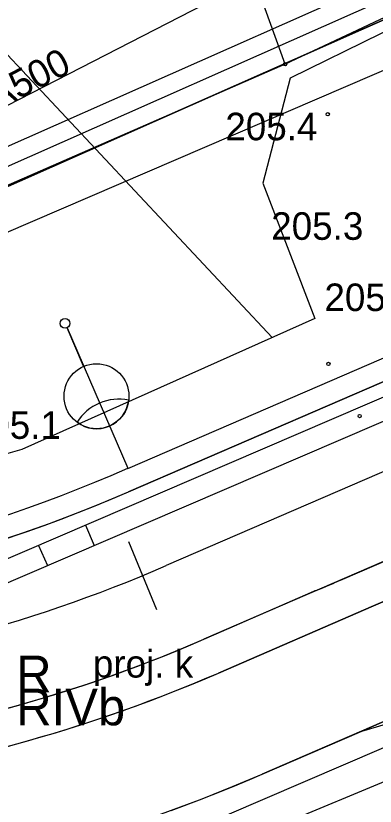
# Model space of a CAD drawing. Extents: x 6512606 to 6513006, y 6022524 to 6022728.
# Drawn here: x 6512832.56 to 6512842.35, y 6022578.56 to 6022600.08 of the extents above; entities that cross this region are included whole.
import ezdxf

# ---------------------------------------------------------------- set-up
doc = ezdxf.new("R2010")
doc.units = 0
for name, color, linetype in [('209-oznaczenie konturu klasyfikacyjnego', 7, 'Continuous'), ('210-oznaczenie konturu użytku gruntowego', 7, 'Continuous'), ('217-kontur klasyfikacyjny', 7, 'Continuous'), ('218-kontur użytku gruntowego', 7, 'Continuous'), ('219-działka ewidencyjna', 7, 'Continuous'), ('4', 7, 'Continuous'), ('Default', 7, 'Continuous'), ('E_OSW_KABLE', 7, 'Continuous'), ('E_OSW_LAMPA', 7, 'Continuous'), ('kolor_kostka_bet', 7, 'Continuous'), ('kolor_sc_rowerowa', 7, 'Continuous'), ('Level 60', 7, 'Continuous'), ('maxp_inst_energ', 7, 'Continuous'), ('maxp_kan_deszczowa', 7, 'Continuous'), ('maxp_krawężnik', 7, 'Continuous'), ('maxp_obrzeże', 7, 'Continuous'), ('maxp_opisy', 7, 'Continuous'), ('maxp_os', 7, 'Continuous'), ('maxp_ramka_2', 7, 'Continuous'), ('ogrodzenie trwałe', 7, 'Continuous'), ('pikieta naturalna', 7, 'Continuous'), ('pikieta naturalna-Atr2', 7, 'Continuous'), ('przewód kanalizacyjny', 7, 'Continuous'), ('przewód kanalizacyjny-Atr1', 7, 'Continuous'), ('punkt wysokościowy naturalny', 7, 'Continuous'), ('punkt wysokościowy naturalny-Atr2', 7, 'Continuous'), ('urządzenie techniczne projektowane lub w budowie (sieć kanalizacyjna) - powierzchnia - ob. projektowany', 7, 'Continuous'), ('urządzenie techniczne projektowane lub w budowie (sieć kanalizacyjna) - powierzchnia - ob. projektowany-Atr17', 7, 'Continuous')]:
    doc.layers.add(name, color=color, linetype=linetype)

# ---------------------------------------------------------------- blocks, each defined once
blk = doc.blocks.new('PW01')
at = {"layer": 'Default'}
blk.add_circle((0, 0), 0.45, dxfattribs=at)

msp = doc.modelspace()

# ---------------------------------------------------------------- linework, layer by layer
at = {"layer": '217-kontur klasyfikacyjny'}
for points in [[(6512811.09, 6022586.02), (6512848.55, 6022602.62)], [(6512848.55, 6022602.62), (6512811.09, 6022586.02)]]:
    msp.add_lwpolyline(points, dxfattribs=at)
at = {"layer": '218-kontur użytku gruntowego'}
for points in [[(6512811.09, 6022586.02), (6512848.55, 6022602.62)], [(6512848.55, 6022602.62), (6512811.09, 6022586.02)]]:
    msp.add_lwpolyline(points, dxfattribs=at)
at = {"layer": '219-działka ewidencyjna'}
msp.add_lwpolyline([(6512811.09, 6022586.02), (6512848.55, 6022602.62)], dxfattribs=at)
at = {"layer": '4'}
msp.add_lwpolyline([(6512811.09, 6022586.02), (6512848.55, 6022602.62)], dxfattribs=at)
at = {"layer": 'E_OSW_KABLE'}
for p, q in [((6512835.613, 6022587.752), (6512849.902, 6022593.935)), ((6512833.956, 6022591.584), (6512835.61, 6022587.761))]:
    msp.add_line(p, q, dxfattribs=at)
msp.add_arc((6512819.75, 6022623.828), 39.4, 271.0457, 293.7363, dxfattribs=at)
at = {"layer": 'E_OSW_LAMPA'}
msp.add_line((6512834.406, 6022590.54), (6512833.956, 6022591.584), dxfattribs=at)
for centre, radius in [((6512833.903, 6022591.705), 0.132), ((6512834.759, 6022589.721), 0.885)]:
    msp.add_circle(centre, radius, dxfattribs=at)
for centre, radius, start, end in [((6512835.378, 6022588.28), 1.362, 79.0115, 147.4701), ((6512834.759, 6022589.721), 0.885, 233.2408, 353.2408)]:
    msp.add_arc(centre, radius, start, end, dxfattribs=at)
at = {"layer": 'kolor_kostka_bet'}
for p, q in [((6512820.033, 6022589.983), (6512848.55, 6022602.62)), ((6512846.547, 6022591.839), (6512835.634, 6022587.117)), ((6512835.634, 6022587.117), (6512845.097, 6022591.211)), ((6512841.472, 6022584.74), (6512843.862, 6022585.774)), ((6512842.307, 6022584.011), (6512846.363, 6022585.766)), ((6512838.022, 6022583.247), (6512840.598, 6022584.378)), ((6512840.926, 6022584.517), (6512840.935, 6022584.514)), ((6512837.685, 6022583.102), (6512838.022, 6022583.247)), ((6512843.498, 6022581.258), (6512839.274, 6022579.431))]:
    msp.add_line(p, q, dxfattribs=at)
for points in [[(6512848.55, 6022602.62), (6512826.343, 6022592.779), (6512820.033, 6022589.983)], [(6512843.862, 6022585.774), (6512841.909, 6022584.929), (6512841.472, 6022584.74)], [(6512841.472, 6022584.74), (6512840.937, 6022584.508), (6512840.931, 6022584.506), (6512840.931, 6022584.506), (6512840.604, 6022584.364), (6512838.022, 6022583.247), (6512837.686, 6022583.102)], [(6512840.928, 6022584.511), (6512840.926, 6022584.517)], [(6512838.083, 6022582.184), (6512838.083, 6022582.184), (6512838.083, 6022582.184), (6512842.307, 6022584.011)], [(6512837.686, 6022583.102), (6512837.685, 6022583.102)]]:
    msp.add_lwpolyline(points, dxfattribs=at)
for centre, radius, start, end in [((6512819.75, 6022623.828), 40, 270.7527, 293.397), ((6512819.75, 6022623.828), 40, 270.7527, 293.397), ((6512829.559, 6022612.273), 30, 292.2834, 293.397), ((6512829.559, 6022612.273), 30, 293.3968, 293.397), ((6512829.559, 6022612.273), 30, 291.5902, 292.2701), ((6512821.802, 6022619.813), 40, 257.9783, 293.3967), ((6512821.802, 6022619.813), 40, 257.9783, 293.3967), ((6512821.802, 6022619.813), 41, 257.9783, 293.3967), ((6512821.802, 6022619.813), 44, 262.7977, 293.3967), ((6512821.802, 6022619.813), 44, 293.3967, 293.397)]:
    msp.add_arc(centre, radius, start, end, dxfattribs=at)
at = {"layer": 'kolor_sc_rowerowa'}
for p, q in [((6512846.363, 6022585.766), (6512842.307, 6022584.011)), ((6512842.307, 6022584.011), (6512838.083, 6022582.184)), ((6512839.274, 6022579.431), (6512843.498, 6022581.258))]:
    msp.add_line(p, q, dxfattribs=at)
msp.add_lwpolyline([(6512839.274, 6022579.431), (6512839.274, 6022579.43), (6512839.274, 6022579.43)], dxfattribs=at)
for radius, start, end in [(41, 257.9783, 293.397), (44, 262.7977, 293.3967), (44, 293.3967, 293.397), (44, 293.3967, 293.397)]:
    msp.add_arc((6512821.802, 6022619.813), radius, start, end, dxfattribs=at)
at = {"layer": 'Level 60'}
msp.add_lwpolyline([(6512835.635, 6022585.762), (6512836.397, 6022583.913)], dxfattribs=at)
at = {"layer": 'maxp_inst_energ'}
msp.add_line((6512828.214, 6022573.256), (6512855.354, 6022584.531), dxfattribs=at)
at = {"layer": 'maxp_kan_deszczowa'}
for points in [[(6512844.992, 6022600.824), (6512840.035, 6022598.38), (6512839.288, 6022595.519), (6512840.706, 6022591.84), (6512832.721, 6022588.268), (6512829.602, 6022587.385)], [(6512836.79, 6022578.444), (6512837.639, 6022578.762), (6512838.466, 6022579.091), (6512839.274, 6022579.43), (6512840.134, 6022579.803), (6512841.985, 6022580.604), (6512845.089, 6022581.521)]]:
    msp.add_lwpolyline(points, dxfattribs=at)
at = {"layer": 'maxp_krawężnik'}
for p, q in [((6512845.097, 6022591.211), (6512835.634, 6022587.117)), ((6512846.884, 6022587.081), (6512841.909, 6022584.929)), ((6512841.909, 6022584.929), (6512837.685, 6022583.102))]:
    msp.add_line(p, q, dxfattribs=at)
for centre, start in [((6512819.75, 6022623.828), 266.9005), ((6512821.802, 6022619.813), 262.7977)]:
    msp.add_arc(centre, 40, start, 293.397, dxfattribs=at)
at = {"layer": 'maxp_obrzeże'}
for p, q in [((6512846.363, 6022585.766), (6512842.307, 6022584.011)), ((6512842.307, 6022584.011), (6512838.083, 6022582.184)), ((6512843.498, 6022581.258), (6512839.274, 6022579.43))]:
    msp.add_line(p, q, dxfattribs=at)
for radius in [41, 44]:
    msp.add_arc((6512821.802, 6022619.813), radius, 262.7977, 293.397, dxfattribs=at)
at = {"layer": 'maxp_opisy'}
msp.add_line((6512839.545, 6022591.321), (6512830.726, 6022600.726), dxfattribs=at)
at = {"layer": 'maxp_os'}
msp.add_line((6512859.416, 6022594.955), (6512836.66, 6022585.109), dxfattribs=at)
msp.add_arc((6512820.776, 6022621.82), 40, 257.9783, 293.397, dxfattribs=at)
at = {"layer": 'maxp_ramka_2'}
for p, q in [((6512819.784, 6022590.966), (6512849.104, 6022603.959)), ((6512819.908, 6022590.475), (6512848.827, 6022603.29))]:
    msp.add_line(p, q, dxfattribs=at)
at = {"layer": 'ogrodzenie trwałe'}
for points in [[(6512847.46, 6022602.32), (6512839.9, 6022598.76), (6512838.38, 6022602.97)], [(6512839.9, 6022598.76), (6512827.97, 6022593.56), (6512815.03, 6022587.35), (6512805.68, 6022582.71), (6512799.86, 6022579.98), (6512797.99, 6022580.48)]]:
    msp.add_lwpolyline(points, dxfattribs=at)
at = {"layer": 'przewód kanalizacyjny'}
msp.add_lwpolyline([(6512821.92, 6022592.3), (6512839.38, 6022601.27), (6512844.43, 6022605.49), (6512845.59, 6022604.41), (6512846.7, 6022605.53), (6512847.74, 6022606.78)], dxfattribs=at)
at = {"layer": 'urządzenie techniczne projektowane lub w budowie (sieć kanalizacyjna) - powierzchnia - ob. projektowany'}
for points in [[(6512813.61, 6022586.15), (6512845.46, 6022599.83)], [(6512848.68, 6022592.32), (6512816.84, 6022578.64)], [(6512817.02, 6022578.07), (6512848.86, 6022591.74)], [(6512834.46, 6022586.21), (6512834.7, 6022585.66)], [(6512833.18, 6022585.66), (6512833.42, 6022585.11)], [(6512852.09, 6022584.23), (6512820.25, 6022570.56)]]:
    msp.add_lwpolyline(points, dxfattribs=at)

# ---------------------------------------------------------------- block references
at = {"layer": 'pikieta naturalna', "xscale": 0.1, "yscale": 0.10000000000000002}
for p in [(6512839.9, 6022598.76), (6512841.06, 6022597.4)]:
    msp.add_blockref('PW01', p, dxfattribs=at)
at = {"layer": 'punkt wysokościowy naturalny', "xscale": 0.1, "yscale": 0.10000000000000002}
for p in [(6512841.08, 6022590.6), (6512841.93, 6022589.18)]:
    msp.add_blockref('PW01', p, dxfattribs=at)

# ---------------------------------------------------------------- texts
at = {"layer": '209-oznaczenie konturu klasyfikacyjnego'}
msp.add_text('RIVb', height=1, dxfattribs=at).set_placement((6512832.57, 6022580.76))
at = {"layer": '210-oznaczenie konturu użytku gruntowego'}
msp.add_text('R', height=1, dxfattribs=at).set_placement((6512832.57, 6022581.66))
at = {"layer": 'pikieta naturalna-Atr2'}
for s, p in [('205.4', (6512838.27, 6022596.69)), ('205.3', (6512839.52, 6022593.98))]:
    msp.add_text(s, height=0.75, dxfattribs=at).set_placement(p)
at = {"layer": 'przewód kanalizacyjny-Atr1'}
msp.add_text('kdA500', height=0.75, rotation=27.192, dxfattribs=at).set_placement((6512831.09, 6022597.01))
at = {"layer": 'punkt wysokościowy naturalny-Atr2'}
for s, p in [('205.3', (6512840.97, 6022592.04)), ('205.1', (6512831.28, 6022588.56))]:
    msp.add_text(s, height=0.75, dxfattribs=at).set_placement(p)
at = {"layer": 'urządzenie techniczne projektowane lub w budowie (sieć kanalizacyjna) - powierzchnia - ob. projektowany-Atr17'}
msp.add_text('proj. k', height=0.75, dxfattribs=at).set_placement((6512834.66, 6022582.06))

doc.saveas('drawing.dxf')
